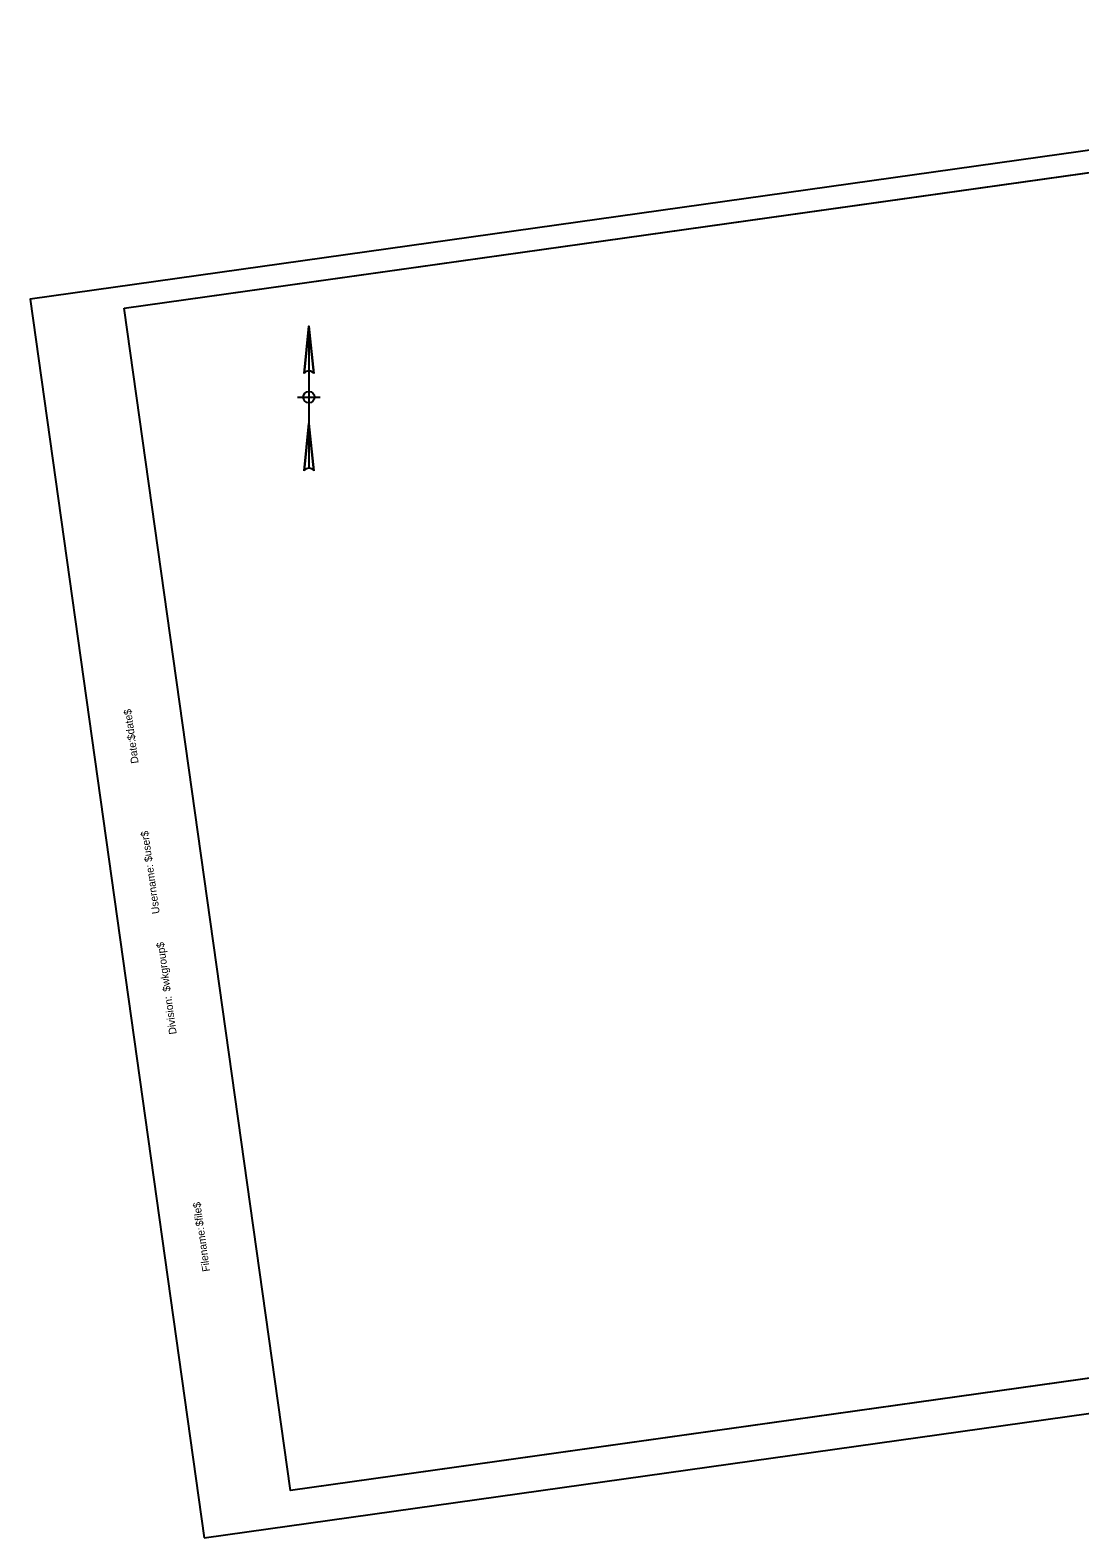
# Model space of a CAD drawing. Extents: x 1760417 to 1761340, y 481137 to 481800.
# Drawn here: x 1760417 to 1760878, y 481137 to 481800 of the extents above; entities that cross this region are included whole.
import ezdxf

# ---------------------------------------------------------------- set-up
doc = ezdxf.new("R2010")
doc.units = 0
for name, color, linetype in [('BORDER', 7, 'Continuous'), ('CLIPS', 7, 'Continuous'), ('H_V CONTROLS', 7, 'Continuous'), ('PLOT BOUNDARY', 7, 'Continuous')]:
    doc.layers.add(name, color=color, linetype=linetype)

msp = doc.modelspace()

# ---------------------------------------------------------------- linework, layer by layer
at = {"layer": 'BORDER'}
msp.add_lwpolyline([(1760457.94, 481677.41), (1761250.16, 481788.75), (1761323.22, 481268.86), (1760531.01, 481157.52)], close=True, dxfattribs=at)
at = {"layer": 'CLIPS'}
msp.add_lwpolyline([(1760457.94, 481677.41), (1761200.64, 481781.79), (1761273.71, 481261.9), (1760531.01, 481157.52)], close=True, dxfattribs=at)
at = {"layer": 'H_V CONTROLS'}
for p, q in [((1760537.09, 481648.75), (1760539.17, 481669.58)), ((1760539.17, 481669.58), (1760539.17, 481607.08)), ((1760539.17, 481669.58), (1760541.25, 481648.75)), ((1760534.17, 481638.33), (1760544.17, 481638.33)), ((1760537.09, 481605.97), (1760539.17, 481626.8)), ((1760539.17, 481626.8), (1760541.25, 481605.97))]:
    msp.add_line(p, q, dxfattribs=at)
for points in [[(1760541.25, 481648.75), (1760539.17, 481669.58), (1760538.13, 481659.17), (1760537.09, 481648.75)], [(1760541.25, 481605.97), (1760539.17, 481626.8), (1760538.13, 481616.38), (1760537.09, 481605.97)]]:
    msp.add_lwpolyline(points, dxfattribs=at)
msp.add_circle((1760539.17, 481638.33), 2.5, dxfattribs=at)
for centre in [(1760539.17, 481647.37), (1760539.17, 481647.37), (1760539.17, 481604.58), (1760539.17, 481604.58)]:
    msp.add_arc(centre, 2.5, 33.55731, 146.44269, dxfattribs=at)
at = {"layer": 'PLOT BOUNDARY'}
msp.add_lwpolyline([(1760493.06, 481136.74), (1761334.79, 481255.04), (1761258.25, 481799.68), (1760416.52, 481681.39)], close=True, dxfattribs=at)

# ---------------------------------------------------------------- texts
at = {"layer": 'BORDER'}
for s, p in [('$date$', (1760462.81, 481487.77)), ('Date:', (1760464.26, 481477.43)), ('$user$', (1760470.33, 481434.22)), ('Username:', (1760473.55, 481411.33)), ('$wkgroup$', (1760478.35, 481377.18)), ('Division:', (1760481, 481358.34)), ('$file$', (1760492.85, 481273.97)), ('Filename:', (1760495.66, 481254.03))]:
    msp.add_text(s, height=3.348, rotation=98, dxfattribs=at).set_placement(p)

doc.saveas('drawing.dxf')
